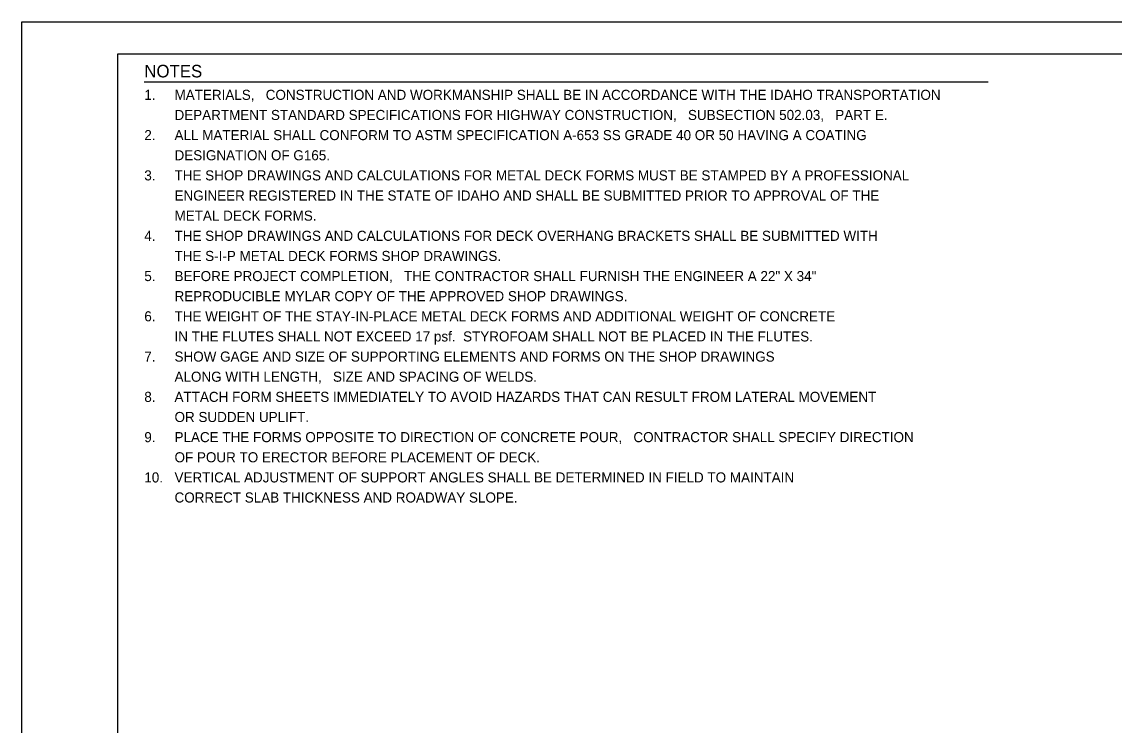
# Model space of a CAD drawing. Extents: x 0 to 34, y 0 to 23.5.
# Drawn here: x 0 to 17.1, y 11 to 22 of the extents above; entities that cross this region are included whole.
import ezdxf

# ---------------------------------------------------------------- set-up
doc = ezdxf.new("R2010")
doc.units = 0
for name, color, linetype in [('BORDER_ANNO_Cutsheet', 7, 'Continuous'), ('BRDG_ANNO_Anno-Sheet', 7, 'Continuous'), ('BRDG_ANNO_General-Notes', 7, 'Continuous')]:
    doc.layers.add(name, color=color, linetype=linetype)

msp = doc.modelspace()

# ---------------------------------------------------------------- linework, layer by layer
at = {"layer": 'BORDER_ANNO_Cutsheet'}
msp.add_lwpolyline([(0, 22), (34, 22), (34, 0), (0, 0)], close=True, dxfattribs=at)
at = {"layer": 'BRDG_ANNO_Anno-Sheet'}
msp.add_lwpolyline([(1.5, 21.5), (33.5, 21.5), (33.5, 0.5), (1.5, 0.5)], close=True, dxfattribs=at)
at = {"layer": 'BRDG_ANNO_General-Notes'}
msp.add_line((1.917, 21.061), (15.124, 21.061), dxfattribs=at)

# ---------------------------------------------------------------- texts
for s, height, p in [('NOTES', 0.1968, (1.917, 21.131)), ('1.', 0.1574, (1.917, 20.78)), ('MATERIALS,   CONSTRUCTION AND WORKMANSHIP SHALL BE IN ACCORDANCE WITH THE IDAHO TRANSPORTATION', 0.15746, (2.39, 20.78)), ('DEPARTMENT STANDARD SPECIFICATIONS FOR HIGHWAY CONSTRUCTION,   SUBSECTION 502.03,   PART E.', 0.15746, (2.39, 20.465)), ('2.', 0.1575, (1.917, 20.15)), ('ALL MATERIAL SHALL CONFORM TO ASTM SPECIFICATION A-653 SS GRADE 40 OR 50 HAVING A COATING', 0.15746, (2.39, 20.15)), ('DESIGNATION OF G165.', 0.15746, (2.39, 19.835)), ('3.', 0.1575, (1.917, 19.52)), ('THE SHOP DRAWINGS AND CALCULATIONS FOR METAL DECK FORMS MUST BE STAMPED BY A PROFESSIONAL', 0.15745, (2.39, 19.52)), ('ENGINEER REGISTERED IN THE STATE OF IDAHO AND SHALL BE SUBMITTED PRIOR TO APPROVAL OF THE', 0.15745, (2.39, 19.205)), ('METAL DECK FORMS.', 0.15745, (2.39, 18.89)), ('4.', 0.1575, (1.917, 18.575)), ('THE SHOP DRAWINGS AND CALCULATIONS FOR DECK OVERHANG BRACKETS SHALL BE SUBMITTED WITH', 0.15745, (2.39, 18.575)), ('THE S-I-P METAL DECK FORMS SHOP DRAWINGS.', 0.15745, (2.39, 18.26)), ('5.', 0.1575, (1.917, 17.945)), ('BEFORE PROJECT COMPLETION,   THE CONTRACTOR SHALL FURNISH THE ENGINEER A 22" X 34"', 0.15745, (2.39, 17.945)), ('REPRODUCIBLE MYLAR COPY OF THE APPROVED SHOP DRAWINGS.', 0.15745, (2.39, 17.631)), ('6.', 0.1575, (1.917, 17.316)), ('THE WEIGHT OF THE STAY-IN-PLACE METAL DECK FORMS AND ADDITIONAL WEIGHT OF CONCRETE', 0.15745, (2.39, 17.316)), ('IN THE FLUTES SHALL NOT EXCEED 17 psf.  STYROFOAM SHALL NOT BE PLACED IN THE FLUTES.', 0.15746, (2.39, 17.001)), ('7.', 0.1575, (1.917, 16.686)), ('SHOW GAGE AND SIZE OF SUPPORTING ELEMENTS AND FORMS ON THE SHOP DRAWINGS', 0.15745, (2.39, 16.686)), ('ALONG WITH LENGTH,   SIZE AND SPACING OF WELDS.', 0.15745, (2.39, 16.371)), ('8.', 0.1575, (1.917, 16.056)), ('ATTACH FORM SHEETS IMMEDIATELY TO AVOID HAZARDS THAT CAN RESULT FROM LATERAL MOVEMENT', 0.15745, (2.39, 16.056)), ('OR SUDDEN UPLIFT.', 0.15745, (2.39, 15.741)), ('9.', 0.1575, (1.917, 15.426)), ('PLACE THE FORMS OPPOSITE TO DIRECTION OF CONCRETE POUR,   CONTRACTOR SHALL SPECIFY DIRECTION', 0.15746, (2.39, 15.426)), ('OF POUR TO ERECTOR BEFORE PLACEMENT OF DECK.', 0.15745, (2.39, 15.111)), ('10.', 0.1575, (1.917, 14.796)), ('VERTICAL ADJUSTMENT OF SUPPORT ANGLES SHALL BE DETERMINED IN FIELD TO MAINTAIN', 0.15745, (2.39, 14.796)), ('CORRECT SLAB THICKNESS AND ROADWAY SLOPE.', 0.15745, (2.39, 14.482))]:
    msp.add_text(s, height=height, dxfattribs=at).set_placement(p)

doc.saveas('drawing.dxf')
